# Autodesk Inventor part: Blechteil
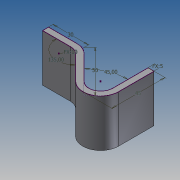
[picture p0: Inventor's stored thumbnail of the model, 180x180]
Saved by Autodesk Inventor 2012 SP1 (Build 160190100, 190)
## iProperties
Created: 2012-02
Part Number: Blechteil
Material: Standard
Document SubType Name: Blech
Designer: Udo.Huebner
Density: 1 g/cm^3
Flat Pattern Width: 4 cm
Flat Pattern Length: 12.0901 cm
Flat Pattern Area: 48.3604 cm^2
Sheet Metal Rule: Standard_mm
Sheet Metal Width: 40,000 mm
Sheet Metal Length: 120,901 mm
Sheet Metal Area: 4836,041 mm^2
Author: Udo.Huebner
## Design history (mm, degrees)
sketch "Skizze1"
  geometry: L1 (0, 0)-(0, 30); L2 (-25.607, -10.607)-(-45.962, 9.749); L3 (-53.033, 12.678)-(-76.82, 12.678); L4 (-76.82, 12.678)-(-76.82, 17.678); L5 (-76.82, 17.678)-(-53.033, 17.678); L6 (-42.426, 13.284)-(-22.071, -7.071); L7 (-5, 0)-(-5, 30); L8 (-5, 30)-(0, 30); L9 (-53.033, 17.678)-(-46.82, 17.678); L10 (-42.426, 13.284)-(-46.82, 17.678); L11 (-22.071, -7.071)-(-11.464, -17.678); L12 (-4.393, -10.607)-(-11.464, -17.678); A1 r 15 centre (-15, 0) between (-25.607, -10.607) and (0, 0); A2 r 10 centre (-53.033, 2.678) between (-45.962, 9.749) and (-53.033, 12.678); A3 r 15 centre (-53.033, 2.678) between (-42.426, 13.284) and (-53.033, 17.678); A4 r 10 centre (-15, 0) between (-22.071, -7.071) and (-5, 0)
  constraints: 24 end point, 12 tangent, 9 point on circle, 4 centre point, 4 perpendicular, 2 collinear, 2 concentric, 2 parallel, 1 equal radius, 1 vertical
  dimensions: "d0" = 5 distance of L7.end L1.end (= Stärke); "d1" = 10 radius of A2 (= 2 x Stärke); "d2" = 45 deg angle of L7 L6; "d3" = 135 deg angle of L3 L2; "d4" = 30 distance from line of L9.end L4; "d5" = 45 dimension on A1 L8; "d6" = 50 distance from line of L12 L9.end
extrude "Extrusion1" join sketch "Skizze1" distance "d7" = 40; taper "d8" = 0 deg
node "Volumenkörper1"
feature "Definition1"
other parameters: "Stärke" = 5 (derived), "KFaktor" = 4.4, "Biegeradius" = 5 (= Stärke), "BreiteBiegungsfreistellung" = 5 (= Stärke), "TiefeBiegungsfreistellung" = 2.5 (= 0.5 x Stärke), "AbstandVerbindung" = 0.01, "Übergangsradius" = 5 (= Biegeradius), "JacobiRadiusGröße" = 5 (= Biegeradius), "Abstandsgröße" = 5 (= Stärke), "Abstandsgröße" = 5, "Biegeradius" = 5, "BreiteBiegungsfreistellung" = 5, "JacobiRadiusGröße" = 5, "Stärke" = 5, "TiefeBiegungsfreistellung" = 2.5, "Übergangsradius" = 5
